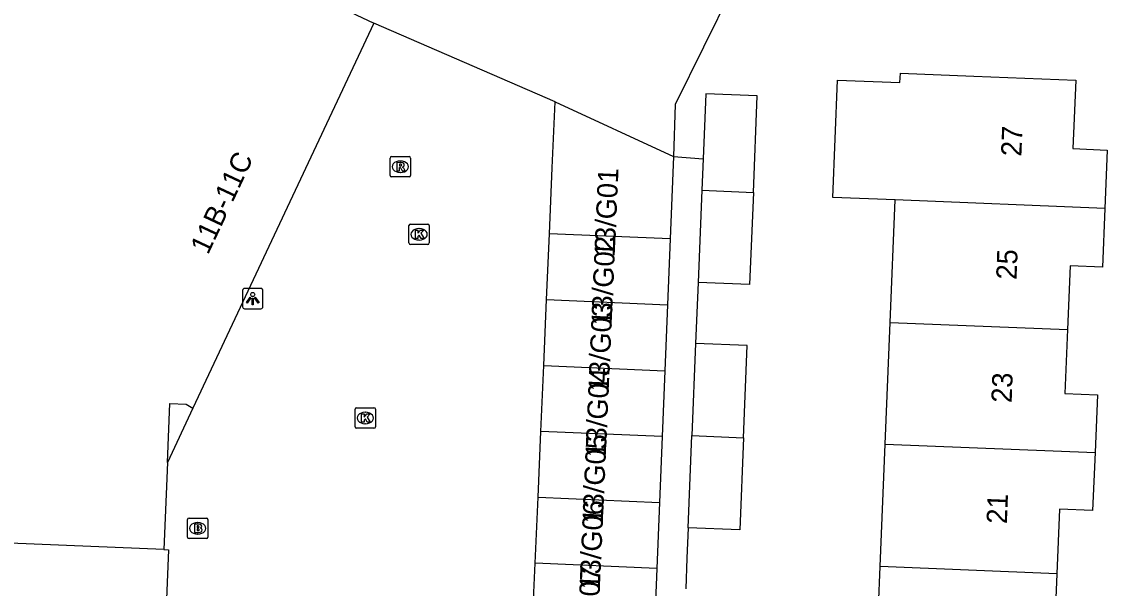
# Model space of a CAD drawing. Extents: x 161355 to 162026, y 386504 to 387459.
# Drawn here: x 161679.6 to 161732.9, y 386881.9 to 386909.7 of the extents above; entities that cross this region are included whole.
import ezdxf

# ---------------------------------------------------------------- set-up
doc = ezdxf.new("R2010")
doc.units = 0
for name, color, linetype in [('IMGEO_Brandkraan', 7, 'Continuous'), ('IMGEO_Kolk', 7, 'Continuous'), ('IMGEO_Lichtpunt', 7, 'Continuous'), ('IMGEO_Pand', 7, 'Continuous'), ('IMGEO_Pand_nummerreeks', 7, 'Continuous'), ('IMGEO_Rijbaan_lokaal_open', 7, 'Continuous'), ('IMGEO_Rioolput', 7, 'Continuous'), ('IMGEO_Voetpad_open', 7, 'Continuous')]:
    doc.layers.add(name, color=color, linetype=linetype)

msp = doc.modelspace()

# ---------------------------------------------------------------- linework, layer by layer
at = {"layer": 'IMGEO_Brandkraan'}
for p, q in [((161687.845, 386885.336), (161688.697, 386885.336)), ((161687.77, 386884.41), (161687.77, 386885.262)), ((161688.258, 386885.116), (161688.283, 386885.116)), ((161688.771, 386885.262), (161688.771, 386884.41)), ((161688.697, 386884.336), (161687.845, 386884.336)), ((161688.281, 386884.556), (161688.256, 386884.556))]:
    msp.add_line(p, q, dxfattribs=at)
for points in [[(161687.845, 386885.336), (161688.697, 386885.336)], [(161687.77, 386884.41), (161687.77, 386885.262)], [(161688.118, 386885.036), (161688.118, 386884.636), (161688.331, 386884.636)], [(161688.349, 386885.036), (161688.118, 386885.036)], [(161688.297, 386884.955), (161688.243, 386884.955), (161688.243, 386884.879)], [(161688.243, 386884.879), (161688.296, 386884.879)], [(161688.305, 386884.803), (161688.243, 386884.803), (161688.243, 386884.722)], [(161688.771, 386885.262), (161688.771, 386884.41)], [(161688.697, 386884.336), (161687.845, 386884.336)], [(161688.243, 386884.722), (161688.305, 386884.722)]]:
    msp.add_lwpolyline(points, dxfattribs=at)
for centre, radius, start, end in [((161687.847, 386885.26), 0.0765, 91.552, 178.448), ((161687.847, 386885.26), 0.0765, 91.552, 178.448), ((161688.695, 386885.26), 0.0765, 1.552, 88.448), ((161688.695, 386885.26), 0.0765, 1.552, 88.448), ((161688.298, 386884.917), 0.0379, 267.8285, 90.9355), ((161688.306, 386884.762), 0.0404, 269.8759, 90.5077), ((161688.353, 386884.891), 0.145, 59.4692, 91.5367), ((161688.378, 386884.938), 0.0922, 285.5137, 58.1501), ((161688.383, 386884.746), 0.105, 301.3115, 78.989), ((161687.847, 386884.412), 0.0765, 181.552, 268.448), ((161687.847, 386884.412), 0.0765, 181.552, 268.448), ((161688.337, 386884.887), 0.251, 268.6676, 293.5347), ((161688.695, 386884.412), 0.0765, 271.552, 358.448), ((161688.695, 386884.412), 0.0765, 271.552, 358.448)]:
    msp.add_arc(centre, radius, start, end, dxfattribs=at)
for centre, major_axis, ratio, start_param, end_param in [((161688.257, 386884.836), (-0.387, 0.002), 0.722429, 4.712389, 7.853982), ((161688.282, 386884.836), (-0.39, 0.002), 0.717154, 1.570796, 4.712389)]:
    msp.add_ellipse(centre, major_axis=major_axis, ratio=ratio, start_param=start_param, end_param=end_param, dxfattribs=at)
at = {"layer": 'IMGEO_Kolk'}
for p, q in [((161698.635, 386898.84), (161698.635, 386899.692)), ((161698.71, 386899.766), (161699.562, 386899.766)), ((161699.636, 386899.692), (161699.636, 386898.84)), ((161699.123, 386899.546), (161699.148, 386899.546)), ((161699.562, 386898.766), (161698.71, 386898.766)), ((161699.146, 386898.986), (161699.121, 386898.986)), ((161695.993, 386889.824), (161695.993, 386890.676)), ((161696.068, 386890.75), (161696.92, 386890.75)), ((161696.994, 386890.676), (161696.994, 386889.824)), ((161696.481, 386890.53), (161696.506, 386890.53)), ((161696.92, 386889.75), (161696.068, 386889.75)), ((161696.504, 386889.97), (161696.479, 386889.97))]:
    msp.add_line(p, q, dxfattribs=at)
for points in [[(161698.635, 386898.84), (161698.635, 386899.692)], [(161698.71, 386899.766), (161699.562, 386899.766)], [(161699.636, 386899.692), (161699.636, 386898.84)], [(161698.956, 386899.466), (161699.079, 386899.466), (161699.079, 386899.315), (161699.209, 386899.466), (161699.373, 386899.466), (161699.227, 386899.315), (161699.38, 386899.066), (161699.228, 386899.066), (161699.143, 386899.23), (161699.079, 386899.163), (161699.079, 386899.066), (161698.956, 386899.066), (161698.956, 386899.466)], [(161699.562, 386898.766), (161698.71, 386898.766)], [(161695.993, 386889.824), (161695.993, 386890.676)], [(161696.068, 386890.75), (161696.92, 386890.75)], [(161696.994, 386890.676), (161696.994, 386889.824)], [(161696.314, 386890.45), (161696.437, 386890.45), (161696.437, 386890.299), (161696.567, 386890.45), (161696.731, 386890.45), (161696.585, 386890.299), (161696.738, 386890.05), (161696.586, 386890.05), (161696.501, 386890.214), (161696.437, 386890.147), (161696.437, 386890.05), (161696.314, 386890.05), (161696.314, 386890.45)], [(161696.92, 386889.75), (161696.068, 386889.75)]]:
    msp.add_lwpolyline(points, dxfattribs=at)
for centre, start, end in [((161698.712, 386899.69), 91.552, 178.448), ((161698.712, 386899.69), 91.552, 178.448), ((161699.56, 386899.69), 1.552, 88.448), ((161699.56, 386899.69), 1.552, 88.448), ((161698.712, 386898.842), 181.552, 268.448), ((161698.712, 386898.842), 181.552, 268.448), ((161699.56, 386898.842), 271.552, 358.448), ((161699.56, 386898.842), 271.552, 358.448), ((161696.07, 386890.674), 91.552, 178.448), ((161696.07, 386890.674), 91.552, 178.448), ((161696.918, 386890.674), 1.552, 88.448), ((161696.918, 386890.674), 1.552, 88.448), ((161696.07, 386889.826), 181.552, 268.448), ((161696.07, 386889.826), 181.552, 268.448), ((161696.918, 386889.826), 271.552, 358.448), ((161696.918, 386889.826), 271.552, 358.448)]:
    msp.add_arc(centre, 0.0765, start, end, dxfattribs=at)
for centre, major_axis, ratio, start_param, end_param in [((161699.122, 386899.266), (-0.387, 0.002), 0.722429, 4.712389, 7.853982), ((161699.147, 386899.266), (-0.39, 0.002), 0.717154, 1.570796, 4.712389), ((161696.48, 386890.25), (-0.387, 0.002), 0.722429, 4.712389, 7.853982), ((161696.505, 386890.25), (-0.39, 0.002), 0.717154, 1.570796, 4.712389)]:
    msp.add_ellipse(centre, major_axis=major_axis, ratio=ratio, start_param=start_param, end_param=end_param, dxfattribs=at)
at = {"layer": 'IMGEO_Lichtpunt'}
for p, q in [((161690.471, 386896.514), (161690.471, 386895.707)), ((161690.471, 386896.514), (161690.471, 386895.707)), ((161691.373, 386896.609), (161690.565, 386896.609)), ((161691.373, 386896.609), (161690.565, 386896.609)), ((161691.467, 386895.707), (161691.467, 386896.514)), ((161691.467, 386895.707), (161691.467, 386896.514)), ((161690.565, 386895.613), (161691.373, 386895.613)), ((161690.565, 386895.613), (161691.373, 386895.613))]:
    msp.add_line(p, q, dxfattribs=at)
for points in [[(161690.845, 386896.178), (161690.884, 386896.15), (161690.696, 386895.888), (161690.658, 386895.915), (161690.845, 386896.178)], [(161690.947, 386896.13), (161690.994, 386896.13), (161690.994, 386895.808), (161690.947, 386895.808), (161690.947, 386896.13)], [(161691.057, 386896.15), (161691.095, 386896.177), (161691.282, 386895.915), (161691.243, 386895.887), (161691.057, 386896.15)]]:
    msp.add_lwpolyline(points, dxfattribs=at)
msp.add_circle((161690.97, 386896.312), 0.0994, dxfattribs=at)
for centre, start, end in [((161690.565, 386896.514), 90, 180), ((161690.565, 386896.514), 90, 180), ((161691.373, 386896.514), 0, 90), ((161691.373, 386896.514), 0, 90), ((161690.565, 386895.707), 180, 270), ((161690.565, 386895.707), 180, 270), ((161691.373, 386895.707), 270, 0), ((161691.373, 386895.707), 270, 360)]:
    msp.add_arc(centre, 0.0946, start, end, dxfattribs=at)
at = {"layer": 'IMGEO_Pand'}
for points in [[(161682.11, 386916.624), (161696.917, 386909.634)], [(161712.8, 386915.555), (161715.869, 386914.1), (161711.708, 386905.636), (161711.616, 386903.089)], [(161696.917, 386909.634), (161688.034, 386890.729)], [(161705.811, 386905.766), (161696.917, 386909.634)], [(161722.499, 386900.952), (161719.437, 386901.078), (161719.672, 386906.837), (161722.734, 386906.712), (161722.753, 386907.177), (161726.365, 386907.03), (161731.36, 386906.827), (161731.224, 386903.471), (161732.907, 386903.402), (161732.79, 386900.53)], [(161715.538, 386901.323), (161715.729, 386906.055), (161713.201, 386906.157), (161713.072, 386902.968)], [(161705.531, 386899.297), (161705.671, 386902.532), (161705.811, 386905.766)], [(161705.811, 386905.766), (161711.616, 386903.089)], [(161711.616, 386903.089), (161711.583, 386902.276), (161711.452, 386899.041)], [(161713.072, 386902.968), (161713.01, 386901.427)], [(161713.01, 386901.427), (161712.828, 386896.906)], [(161715.538, 386901.323), (161715.356, 386896.803), (161712.828, 386896.906)], [(161713.01, 386901.427), (161715.538, 386901.323)], [(161722.255, 386894.945), (161722.499, 386900.952)], [(161732.79, 386900.53), (161722.499, 386900.952)], [(161732.79, 386900.53), (161732.673, 386897.661), (161731.083, 386897.726), (161730.956, 386894.588)], [(161705.391, 386896.063), (161705.531, 386899.297)], [(161711.452, 386899.041), (161705.531, 386899.297)], [(161711.452, 386899.041), (161711.322, 386895.806)], [(161705.25, 386892.829), (161705.391, 386896.063)], [(161705.391, 386896.063), (161711.322, 386895.806)], [(161711.322, 386895.806), (161711.191, 386892.572)], [(161722.011, 386888.972), (161722.255, 386894.945)], [(161722.255, 386894.945), (161730.956, 386894.588)], [(161730.956, 386894.588), (161730.828, 386891.448), (161732.42, 386891.383), (161732.305, 386888.55)], [(161712.706, 386893.908), (161712.524, 386889.387)], [(161715.052, 386889.284), (161715.234, 386893.805), (161712.706, 386893.908)], [(161705.11, 386889.595), (161705.25, 386892.829)], [(161705.25, 386892.829), (161711.191, 386892.572)], [(161711.191, 386892.572), (161711.06, 386889.337)], [(161686.785, 386888.069), (161686.903, 386890.968), (161687.708, 386890.936), (161688.034, 386890.729)], [(161704.97, 386886.36), (161705.11, 386889.595)], [(161711.06, 386889.337), (161705.11, 386889.595)], [(161711.06, 386889.337), (161710.93, 386886.102)], [(161712.341, 386884.866), (161712.524, 386889.387)], [(161715.052, 386889.284), (161714.87, 386884.763), (161712.341, 386884.866)], [(161712.524, 386889.387), (161715.052, 386889.284)], [(161721.767, 386882.965), (161722.011, 386888.972)], [(161722.011, 386888.972), (161732.305, 386888.55)], [(161732.305, 386888.55), (161732.189, 386885.715), (161730.554, 386885.782), (161730.424, 386882.61)], [(161686.785, 386888.069), (161686.611, 386883.804)], [(161704.83, 386883.126), (161704.97, 386886.36)], [(161704.97, 386886.36), (161710.93, 386886.102)], [(161710.93, 386886.102), (161710.799, 386882.868)], [(161686.611, 386883.804), (161667.894, 386884.566)], [(161686.611, 386883.804), (161686.837, 386883.781), (161685.674, 386855.268)], [(161704.69, 386879.892), (161704.83, 386883.126)], [(161710.799, 386882.868), (161704.83, 386883.126)], [(161710.799, 386882.868), (161710.668, 386879.633)], [(161721.523, 386876.969), (161721.767, 386882.965)], [(161730.424, 386882.61), (161721.767, 386882.965)], [(161730.424, 386882.61), (161730.295, 386879.439), (161731.974, 386879.371), (161731.859, 386876.545)]]:
    msp.add_lwpolyline(points, dxfattribs=at)
at = {"layer": 'IMGEO_Rijbaan_lokaal_open'}
msp.add_lwpolyline([(161688.034, 386890.729), (161686.785, 386888.069)], dxfattribs=at)
at = {"layer": 'IMGEO_Rioolput'}
for p, q in [((161697.713, 386902.157), (161697.713, 386903.009)), ((161697.788, 386903.083), (161698.64, 386903.083)), ((161698.714, 386903.009), (161698.714, 386902.157)), ((161698.201, 386902.863), (161698.226, 386902.863)), ((161698.64, 386902.083), (161697.788, 386902.083)), ((161698.224, 386902.303), (161698.199, 386902.303))]:
    msp.add_line(p, q, dxfattribs=at)
for points in [[(161697.713, 386902.157), (161697.713, 386903.009)], [(161697.788, 386903.083), (161698.64, 386903.083)], [(161698.714, 386903.009), (161698.714, 386902.157)], [(161698.302, 386902.781), (161698.05, 386902.783), (161698.05, 386902.383)], [(161698.05, 386902.383), (161698.174, 386902.383), (161698.174, 386902.545), (161698.185, 386902.545)], [(161698.228, 386902.702), (161698.174, 386902.702), (161698.174, 386902.621)], [(161698.174, 386902.621), (161698.226, 386902.621)], [(161698.232, 386902.516), (161698.303, 386902.383), (161698.443, 386902.383), (161698.378, 386902.509)], [(161698.64, 386902.083), (161697.788, 386902.083)]]:
    msp.add_lwpolyline(points, dxfattribs=at)
for centre, radius, start, end in [((161697.79, 386903.007), 0.0765, 91.552, 178.448), ((161697.79, 386903.007), 0.0765, 91.552, 178.448), ((161698.638, 386903.007), 0.0765, 1.552, 88.448), ((161698.638, 386903.007), 0.0765, 1.552, 88.448), ((161698.184, 386902.492), 0.0533, 26.0293, 88.6989), ((161698.21, 386902.81), 0.19, 274.7715, 282.9687), ((161698.234, 386902.606), 0.0964, 77.0061, 93.1865), ((161698.248, 386902.663), 0.0378, 276.6634, 79.6772), ((161698.301, 386902.671), 0.109, 350.3612, 89.416), ((161698.299, 386902.671), 0.112, 277.5842, 350.9817), ((161698.283, 386902.456), 0.108, 29.5134, 73.7905), ((161697.79, 386902.159), 0.0765, 181.552, 268.448), ((161697.79, 386902.159), 0.0765, 181.552, 268.448), ((161698.638, 386902.159), 0.0765, 271.552, 358.448), ((161698.638, 386902.159), 0.0765, 271.552, 358.448)]:
    msp.add_arc(centre, radius, start, end, dxfattribs=at)
for centre, major_axis, ratio, start_param, end_param in [((161698.2, 386902.583), (-0.387, 0.002), 0.722429, 4.712389, 7.853982), ((161698.225, 386902.583), (-0.39, 0.002), 0.717154, 1.570796, 4.712389)]:
    msp.add_ellipse(centre, major_axis=major_axis, ratio=ratio, start_param=start_param, end_param=end_param, dxfattribs=at)
at = {"layer": 'IMGEO_Voetpad_open'}
for points in [[(161711.616, 386903.089), (161713.072, 386902.968)], [(161712.828, 386896.906), (161712.767, 386895.407), (161712.706, 386893.908)], [(161712.341, 386884.866), (161712.28, 386883.367), (161712.219, 386881.868)]]:
    msp.add_lwpolyline(points, dxfattribs=at)

# ---------------------------------------------------------------- texts
at = {"layer": 'IMGEO_Pand_nummerreeks'}
for s, rotation, p in [('27', 87.737, (161728.69, 386903.076)), ('11B-11C', 64.8323, (161688.773, 386898.226)), ('13/G01', 87.4495, (161708.729, 386898.124)), ('13/G02', 87.4495, (161708.579, 386894.769)), ('25', 87.7379, (161728.451, 386897.026)), ('13/G03', 87.4495, (161708.435, 386891.535)), ('13/G04', 87.4495, (161708.291, 386888.296)), ('23', 87.7379, (161728.212, 386890.976)), ('13/G05', 87.4495, (161708.147, 386885.056)), ('21', 87.7379, (161727.978, 386885.038)), ('13/G06', 87.4495, (161708.002, 386881.817)), ('13/G07', 87.4495, (161707.858, 386878.577))]:
    msp.add_text(s, height=1, rotation=rotation, dxfattribs=at).set_placement(p)

doc.saveas('drawing.dxf')
